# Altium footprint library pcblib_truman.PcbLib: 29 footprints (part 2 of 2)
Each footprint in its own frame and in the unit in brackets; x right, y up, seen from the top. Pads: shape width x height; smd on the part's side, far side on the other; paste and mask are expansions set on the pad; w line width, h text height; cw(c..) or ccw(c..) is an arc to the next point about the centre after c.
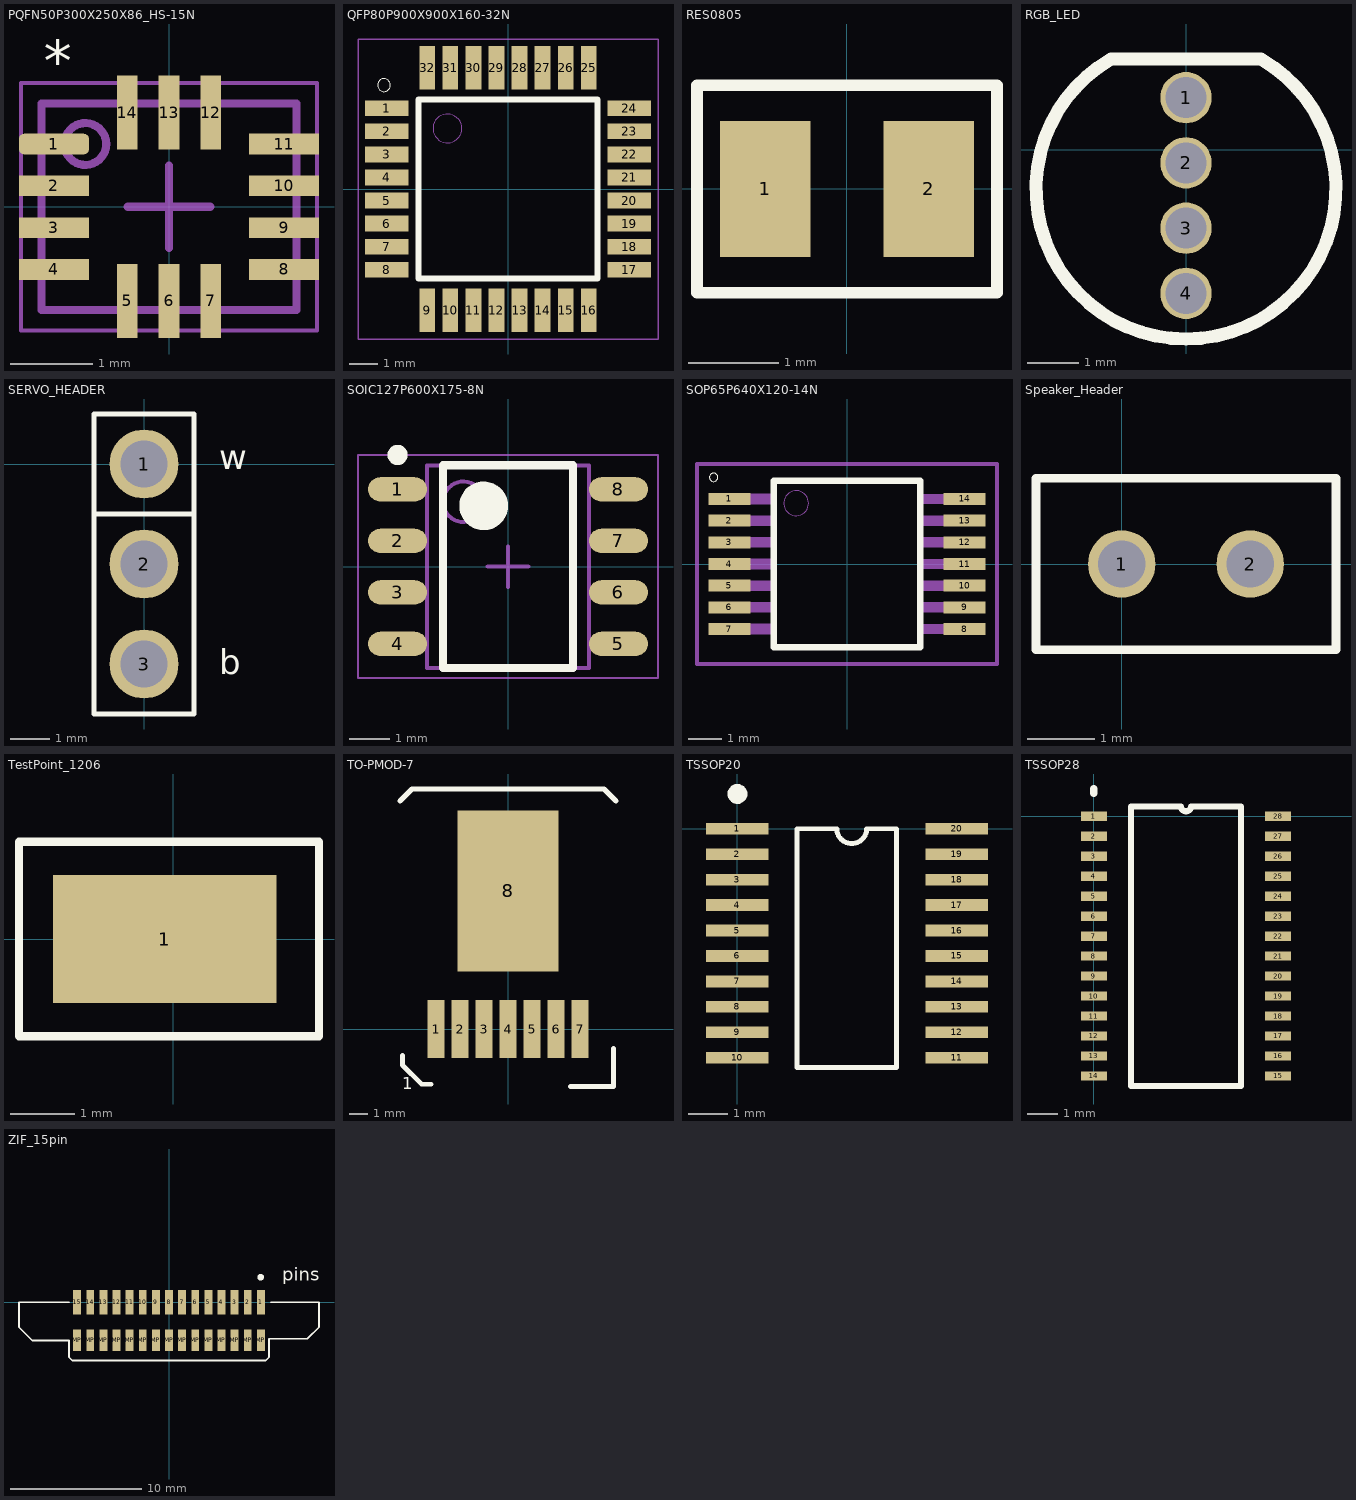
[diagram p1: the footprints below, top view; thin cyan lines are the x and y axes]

## PQFN50P300X250X86_HS-15N [mm] "PQFN, 14-Leads, Body 3.00x2.50mm, Pitch 0.50mm, Thermal Pad 1.45x1.95mm, IPC Medium Density"
height 0.86
pads (14):
  rrect50% 0.85x0.25 smd: 1(-1.397,0.762)
  rect 0.85x0.25 smd: 2(-1.397,0.254) 3(-1.397,-0.254) 4(-1.397,-0.762) 8(1.397,-0.762) 9(1.397,-0.254) 10(1.397,0.254) 11(1.397,0.762)
  rect 0.25x0.9 smd: 5(-0.508,-1.143) 6(0,-1.143) 7(0.508,-1.143) 12(0.508,1.143) 13(0,1.143) 14(-0.508,1.143)
Top Overlay:
  text "*" at -1.524,1.524 h0.5
Mechanical 13:
  circle w0.1: c-1.016,0.762 r0.254
  lines w0.1: -1.55,-1.255 -1.55,1.255 1.55,1.255 1.55,-1.255 -1.55,-1.255
Mechanical 15:
  lines w0.05: -1.8,-1.505 -1.8,1.505 1.8,1.505 1.8,-1.505 -1.8,-1.505
  lines w0.1: -0.5,0 0.5,0 ; 0,-0.5 0,0.5
3D body: height 0.86, standoff 0, extent -1.55,-1.255 1.55,1.255

## QFP80P900X900X160-32N [mm]
pads (32):
  rect 1.5x0.55 smd: 1(-4.2,2.8) 2(-4.2,2) 3(-4.2,1.2) 4(-4.2,0.4) 5(-4.2,-0.4) 6(-4.2,-1.2) 7(-4.2,-2) 8(-4.2,-2.8) 17(4.2,-2.8) 18(4.2,-2) 19(4.2,-1.2) 20(4.2,-0.4) 21(4.2,0.4) 22(4.2,1.2) 23(4.2,2) 24(4.2,2.8)
  rect 0.55x1.5 smd: 9(-2.8,-4.2) 10(-2,-4.2) 11(-1.2,-4.2) 12(-0.4,-4.2) 13(0.4,-4.2) 14(1.2,-4.2) 15(2,-4.2) 16(2.8,-4.2) 25(2.8,4.2) 26(2,4.2) 27(1.2,4.2) 28(0.4,4.2) 29(-0.4,4.2) 30(-1.2,4.2) 31(-2,4.2) 32(-2.8,4.2)
Top Overlay:
  circle w0: c-4.3,3.6 r0.224
  lines w0.2: -3.1,-3.1 3.1,-3.1 3.1,3.1 -3.1,3.1 -3.1,-3.1
Mechanical 1:
  circle w0: c-2.1,2.1 r0.5
  lines w0.05: -5.2,-5.2 5.2,-5.2 5.2,5.2 -5.2,5.2 -5.2,-5.2

## RES0805 [mm]
pads (2):
  rect 1x1.5 smd: 1(-0.9,0) 2(0.9,0)
Top Overlay:
  lines w0.127: -1.651,-1.143 1.651,-1.143 1.651,1.143 -1.651,1.143 -1.651,-1.143

## RGB_LED [mm]
pads (4):
  round 1 hole 0.8: 1(0,1.016) 2(0,-0.254) 3(0,-1.524) 4(0,-2.794)
Top Overlay:
  lines w0.254: -1.46,1.768 ccw(c0,-0.762) 1.461,1.768 -1.46,1.768

## SERVO_HEADER [mm]
pads (3):
  round 1.75 hole 1.2: 1(0,0) 2(0,-2.54) 3(0,-5.08)
Top Overlay:
  lines w0.127: 1.27,-1.27 -1.27,-1.27 -1.27,1.27 ; -1.27,1.27 1.27,1.27 1.27,-6.35 -1.27,-6.35 -1.27,1.27
  text "w" at 1.905,-0.127 h0.64
  text "b" at 1.905,-5.334 h0.64

## SOIC127P600X175-8N [mm] "SOIC, 8-Leads, Body 4.90x3.90mm, Pitch 1.27mm, IPC Medium Density"
height 1.75
pads (8):
  oval 1.45x0.6 smd: 1(-2.725,1.905) 2(-2.725,0.635) 3(-2.725,-0.635) 4(-2.725,-1.905) 5(2.725,-1.905) 6(2.725,-0.635) 7(2.725,0.635) 8(2.725,1.905)
Top Overlay:
  circle w0.25: c-2.725,2.755 r0.125
  circle w0.6: c-0.6,1.5 r0.3
  lines w0.2: -1.6,-2.5 -1.6,2.5 1.6,2.5 1.6,-2.5 -1.6,-2.5
Mechanical 13:
  circle w0.1: c-1.1,1.6 r0.5
  lines w0.1: -2,-2.5 -2,2.5 2,2.5 2,-2.5 -2,-2.5
Mechanical 15:
  lines w0.05: -3.7,-2.75 -3.7,2.75 3.7,2.75 3.7,-2.75 -3.7,-2.75
  lines w0.1: -0.5,0 0.5,0 ; 0,-0.5 0,0.5
3D body: height 1.75, standoff 0.1, extent -2,-2.5 2,2.5

## SOP65P640X120-14N [mm]
pads (14):
  rect 1.26x0.36 smd: 1(-3.53,1.95) 2(-3.53,1.3) 3(-3.53,0.65) 4(-3.53,0) 5(-3.53,-0.65) 6(-3.53,-1.3) 7(-3.53,-1.95) 8(3.53,-1.95) 9(3.53,-1.3) 10(3.53,-0.65) 11(3.53,0) 12(3.53,0.65) 13(3.53,1.3) 14(3.53,1.95)
Top Overlay:
  circle w0: c-4,2.6 r0.127
  lines w0.203: -2.2,-2.5 2.2,-2.5 2.2,2.5 -2.2,2.5 -2.2,-2.5
Mechanical 1:
  circle w0: c-1.525,1.825 r0.375
  region: 2.226,1.801 2.226,2.1 3.2,2.1 3.2,1.801
  region: 2.228,1.153 2.228,1.449 3.201,1.449 3.201,1.153
  region: 2.227,0.502 2.227,0.798 3.202,0.798 3.202,0.502
  region: 2.226,-0.149 2.226,0.148 3.202,0.148 3.202,-0.149
  region: 2.226,-0.799 2.226,-0.503 3.203,-0.503 3.203,-0.799
  region: 2.225,-1.45 2.225,-1.151 3.201,-1.151 3.201,-1.45
  region: 2.225,-2.1 2.225,-1.8 3.2,-1.8 3.2,-2.1
  region: -2.225,-1.8 -2.225,-2.104 -3.204,-2.104 -3.204,-1.8
  region: -2.225,-1.15 -2.225,-1.452 -3.202,-1.452 -3.202,-1.15
  region: -2.226,-0.499 -2.226,-0.802 -3.202,-0.802 -3.202,-0.499
  region: -2.226,0.151 -2.226,-0.151 -3.201,-0.151 -3.201,0.151
  region: -2.228,0.803 -2.228,0.498 -3.202,0.498 -3.202,0.803
  region: -2.225,1.45 -2.225,1.15 -3.2,1.15 -3.2,1.45
  region: -2.227,2.102 -2.227,1.799 -3.201,1.799 -3.201,2.102
  lines w0.127: -4.5,-3 -4.5,3 4.5,3 4.5,-3 -4.5,-3

## Speaker_Header [mm]
pads (2):
  round 1 hole 0.7: 1(0,0) 2(1.905,0)
Top Overlay:
  lines w0.127: -1.27,-1.27 -1.27,1.27 1.016,1.27 3.175,1.27 3.175,-1.27 -1.27,-1.27

## TestPoint_1206 [mm]
pads (1):
  rect 3.5x2 smd: 1(-0.127,0)
Top Overlay:
  lines w0.127: -2.413,-1.524 -2.413,1.524 0,1.524 2.286,1.524 2.286,-1.524 -2.413,-1.524

## TO-PMOD-7 [mm]
pads (8):
  rect 0.89x3.06 smd: 1(-3.81,0) 2(-2.54,0) 3(-1.27,0) 4(0,0) 5(1.27,0) 6(2.54,0) 7(3.81,0)
  rect 5.35x8.54 smd: 8(0,7.305)
Top Overlay:
  lines w0.254: -5.715,12.065 -5.08,12.7 0,12.7 5.08,12.7 5.715,12.065 ; -5.588,-1.397 -5.588,-1.905 -4.572,-2.921 -4.064,-2.921 ; 3.302,-3.048 5.588,-3.048 5.588,-1.016
  text "1" at -5.588,-3.175 h0.64

## TSSOP20 [mm]
pads (20):
  rect 1.6x0.3 smd: 1(0,0) 2(0,-0.65) 3(0,-1.3) 4(0,-1.95) 5(0,-2.6) 6(0,-3.25) 7(0,-3.9) 8(0,-4.55) 9(0,-5.2) 10(0,-5.85) 11(5.6,-5.85) 12(5.6,-5.2) 13(5.6,-4.55) 14(5.6,-3.9) 15(5.6,-3.25) 16(5.6,-2.6) 17(5.6,-1.95) 18(5.6,-1.3) 19(5.6,-0.65) 20(5.6,0)
Top Overlay:
  circle w0.254: c0,0.889 r0.127
  lines w0.127: 1.524,-6.096 4.064,-6.096 4.064,0 3.302,0 cw(c2.921,0) 2.54,0 1.524,0 1.524,-6.096

## TSSOP28 [mm]
pads (28):
  rect 0.85x0.3 smd: 1(0,0) 2(0,-0.65) 3(0,-1.3) 4(0,-1.95) 5(0,-2.6) 6(0,-3.25) 7(0,-3.9) 8(0,-4.55) 9(0,-5.2) 10(0,-5.85) 11(0,-6.5) 12(0,-7.15) 13(0,-7.8) 14(0,-8.45) 15(6,-8.45) 16(6,-7.8) 17(6,-7.15) 18(6,-6.5) 19(6,-5.85) 20(6,-5.2) 21(6,-4.55) 22(6,-3.9) 23(6,-3.25) 24(6,-2.6) 25(6,-1.95) 26(6,-1.3) 27(6,-0.65) 28(6,0)
Top Overlay:
  lines w0.2: 1.21,-8.775 1.21,0.325 2.838,0.325 ccw(c3,0.325) 3.162,0.325 4.79,0.325 4.79,-8.775 1.21,-8.775
  lines w0.254: 0,0.762 0,0.889

## ZIF_15pin [mm]
pads (30):
  rect 0.6x1.85 smd: 1(7,0) 2(6,0) 3(5,0) 4(4,0) 5(3,0) 6(2,0) 7(1,0) 8(0,0) 9(-1,0) 10(-2,0) 11(-3,0) 12(-4,0) 13(-5,0) 14(-6,0) 15(-7,0)
  rect 0.6x1.65 smd: MP(-7,-2.9) MP(-6,-2.9) MP(-5,-2.9) MP(-4,-2.9) MP(-3,-2.9) MP(-2,-2.9) MP(-1,-2.9) MP(0,-2.9) MP(1,-2.9) MP(2,-2.9) MP(3,-2.9) MP(4,-2.9) MP(5,-2.9) MP(6,-2.9) MP(7,-2.9)
Top Overlay:
  circle w0.254: c6.985,1.905 r0.127
  lines w0.127: -7.62,0 -11.43,0 -11.43,-1.905 -10.414,-2.921 -7.62,-2.921 -7.62,-4.191 -7.366,-4.445 7.366,-4.445 7.62,-4.191 7.62,-3.048 7.62,-2.794 10.287,-2.794 10.541,-2.794 11.43,-1.905 11.43,0 7.747,0
  text "pins" at 8.636,1.651 h1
